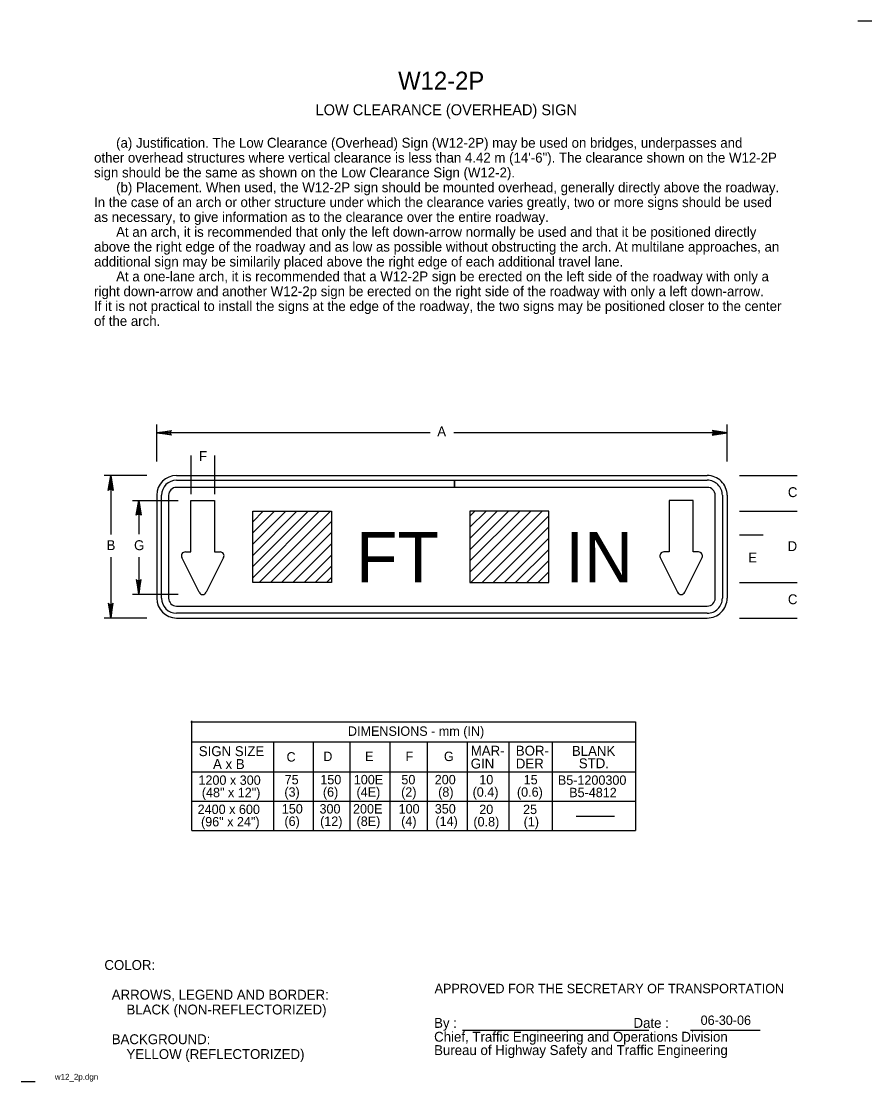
# Model space of a CAD drawing. Extents: x 0.004 to 0.219, y 0.004 to 0.272.
import ezdxf

# ---------------------------------------------------------------- set-up
doc = ezdxf.new("R2010")
doc.units = 0
for name, color, linetype in [('1', 7, 'Continuous'), ('2', 7, 'Continuous'), ('3', 7, 'Continuous'), ('4', 7, 'Continuous'), ('63', 7, 'Continuous')]:
    doc.layers.add(name, color=color, linetype=linetype)

# ---------------------------------------------------------------- blocks, each defined once
blk = doc.blocks.new('RARROW')
at = {"layer": '3'}
for p, q in [((-2.156, 0.28500000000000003), (-2.2665, 0.384625)), ((-2.2665, 0.384625), (0, 0)), ((0, 0), (-2.2665, -0.379125)), ((-2.156, 0.28500000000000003), (-2.075625, 0.12075)), ((0, 0), (-2.156, 0.28500000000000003)), ((-2.14975, -0.2705), (0, 0)), ((-2.075625, 0.12075), (0, 0)), ((0, 0), (-2.074, -0.108)), ((-2.2665, -0.379125), (-2.14975, -0.2705)), ((-2.074, -0.108), (-2.14975, -0.2705))]:
    blk.add_line(p, q, dxfattribs=at)

msp = doc.modelspace()

# ---------------------------------------------------------------- linework, layer by layer
at = {"layer": '1'}
for p, q in [((0.04694523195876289, 0.1620329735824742), (0.04694523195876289, 0.1522708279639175)), ((0.05294523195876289, 0.1620329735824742), (0.05294523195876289, 0.1522708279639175)), ((0.026746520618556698, 0.15700979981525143), (0.026746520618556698, 0.14208944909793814)), ((0.04334899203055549, 0.15580979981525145), (0.1135362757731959, 0.15580979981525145)), ((0.1135362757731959, 0.15580979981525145), (0.1135362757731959, 0.15400979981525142)), ((0.1135362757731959, 0.15400979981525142), (0.1135362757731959, 0.15580979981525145)), ((0.1135362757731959, 0.15580979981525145), (0.17734899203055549, 0.15580979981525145)), ((0.1135362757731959, 0.15400979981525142), (0.04334899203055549, 0.15400979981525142)), ((0.1773489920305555, 0.15400979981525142), (0.1135362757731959, 0.15400979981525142)), ((0.03381359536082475, 0.15070371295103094), (0.03381359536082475, 0.1422092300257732)), ((0.038348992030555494, 0.15200979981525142), (0.038348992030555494, 0.12600979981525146)), ((0.039548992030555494, 0.12600979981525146), (0.039548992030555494, 0.15200979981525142)), ((0.0413489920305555, 0.15200979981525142), (0.0413489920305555, 0.12600979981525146)), ((0.04694523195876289, 0.15071868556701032), (0.05294523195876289, 0.15071868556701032)), ((0.04694523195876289, 0.1377186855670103), (0.04694523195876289, 0.15071868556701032)), ((0.05294523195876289, 0.15071868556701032), (0.0529452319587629, 0.1377186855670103)), ((0.17375275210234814, 0.15071868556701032), (0.16775275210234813, 0.15071868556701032)), ((0.16775275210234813, 0.15071868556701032), (0.16775275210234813, 0.1377186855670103)), ((0.17375275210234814, 0.1377186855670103), (0.17375275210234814, 0.15071868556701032)), ((0.1793489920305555, 0.12600979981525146), (0.17934899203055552, 0.15200979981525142)), ((0.1811489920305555, 0.15200979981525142), (0.18114899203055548, 0.12600979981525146)), ((0.1823489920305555, 0.1520097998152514), (0.1823489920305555, 0.12600979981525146)), ((0.06256101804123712, 0.1453259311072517), (0.06524488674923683, 0.14800979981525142)), ((0.06256101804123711, 0.14249750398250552), (0.06807331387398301, 0.14800979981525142)), ((0.06256101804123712, 0.13966907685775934), (0.07090174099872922, 0.14800979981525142)), ((0.06256101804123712, 0.13684064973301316), (0.07373016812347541, 0.14800979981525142)), ((0.06256101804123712, 0.13401222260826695), (0.07655859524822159, 0.14800979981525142)), ((0.06256101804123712, 0.13118379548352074), (0.07938702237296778, 0.14800979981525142)), ((0.06421544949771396, 0.13000979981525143), (0.08221544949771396, 0.14800979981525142)), ((0.1174206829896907, 0.14675531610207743), (0.1186751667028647, 0.14800979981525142)), ((0.1174206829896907, 0.14392688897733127), (0.12150359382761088, 0.14800979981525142)), ((0.1174206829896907, 0.14109846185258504), (0.12433202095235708, 0.14800979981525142)), ((0.11742068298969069, 0.1382700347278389), (0.12716044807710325, 0.14800979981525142)), ((0.1174206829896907, 0.13544160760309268), (0.12998887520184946, 0.14800979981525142)), ((0.11742068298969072, 0.13261318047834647), (0.13281730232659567, 0.14800979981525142)), ((0.11764572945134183, 0.13000979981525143), (0.13564572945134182, 0.14800979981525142)), ((0.06704387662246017, 0.13000979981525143), (0.08244465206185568, 0.14541057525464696)), ((0.12047415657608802, 0.13000979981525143), (0.13730431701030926, 0.14683996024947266)), ((0.06987230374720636, 0.13000979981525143), (0.08244465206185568, 0.14258214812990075)), ((0.12330258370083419, 0.13000979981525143), (0.13730431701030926, 0.1440115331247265)), ((0.07270073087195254, 0.13000979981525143), (0.08244465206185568, 0.13975372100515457)), ((0.1261310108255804, 0.13000979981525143), (0.13730431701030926, 0.1411831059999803)), ((0.04556326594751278, 0.1377186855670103), (0.04694523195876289, 0.1377186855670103)), ((0.05294523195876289, 0.1377186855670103), (0.05432719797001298, 0.1377186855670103)), ((0.07552915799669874, 0.13000979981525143), (0.08244465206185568, 0.13692529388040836)), ((0.12895943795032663, 0.13000979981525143), (0.13730431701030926, 0.1383546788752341)), ((0.16775275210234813, 0.1377186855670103), (0.16637078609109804, 0.1377186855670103)), ((0.17513471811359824, 0.1377186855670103), (0.17375275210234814, 0.1377186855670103)), ((0.026746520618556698, 0.13633996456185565), (0.026746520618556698, 0.12100979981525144)), ((0.03381359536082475, 0.13633996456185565), (0.03381359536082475, 0.12702699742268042)), ((0.04905080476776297, 0.12750753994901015), (0.04466883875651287, 0.13627147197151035)), ((0.055221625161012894, 0.13627147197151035), (0.0508396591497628, 0.12750753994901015)), ((0.07835758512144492, 0.13000979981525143), (0.08244465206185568, 0.13409686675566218)), ((0.13178786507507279, 0.13000979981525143), (0.13730431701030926, 0.1355262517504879)), ((0.16547635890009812, 0.13627147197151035), (0.1698583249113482, 0.12750753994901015)), ((0.17164717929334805, 0.12750753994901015), (0.17602914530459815, 0.13627147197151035)), ((0.08118601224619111, 0.13000979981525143), (0.0824446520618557, 0.131268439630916)), ((0.134616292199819, 0.13000979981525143), (0.13730431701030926, 0.1326978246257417)), ((0.04334899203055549, 0.12400979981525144), (0.17734899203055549, 0.12400979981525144)), ((0.17734899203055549, 0.12220979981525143), (0.04334899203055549, 0.12220979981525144)), ((0.14420019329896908, 0.07096952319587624), (0.15390244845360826, 0.07096952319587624)), ((0.11556484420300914, 0.01694517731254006), (0.16256818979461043, 0.01694517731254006)), ((0.1730782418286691, 0.01694517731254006), (0.19068984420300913, 0.01694517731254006))]:
    msp.add_line(p, q, dxfattribs=at)
for points in [[(0.08244465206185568, 0.13000979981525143), (0.06256101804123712, 0.13000979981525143), (0.06256101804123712, 0.14800979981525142), (0.08244465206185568, 0.14800979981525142)], [(0.1174206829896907, 0.13000979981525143), (0.13730431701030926, 0.13000979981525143), (0.13730431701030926, 0.14800979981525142), (0.1174206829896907, 0.14800979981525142)]]:
    msp.add_lwpolyline(points, close=True, dxfattribs=at)
for centre, radius, start, end in [((0.04334899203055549, 0.15200979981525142), 0.005, 90, 180), ((0.04334899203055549, 0.15200979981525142), 0.0037999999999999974, 90, 180), ((0.1773489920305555, 0.15200979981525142), 0.005, 1.5631940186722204e-13, 90.00000000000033), ((0.1773489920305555, 0.15200979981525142), 0.0038000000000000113, 0, 90.00000000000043), ((0.04334899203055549, 0.15200979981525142), 0.002, 90, 180), ((0.1773489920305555, 0.15200979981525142), 0.002, 0, 90), ((0.04556326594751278, 0.1367186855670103), 0.001, 90.00000000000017, 206.56505117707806), ((0.05432719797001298, 0.1367186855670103), 0.001, 333.434948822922, 90), ((0.16637078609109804, 0.1367186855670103), 0.001, 90.00000000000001, 206.565051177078), ((0.17513471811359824, 0.1367186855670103), 0.0009999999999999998, 333.4349488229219, 89.99999999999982), ((0.04334899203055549, 0.12600979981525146), 0.005, 180, 270), ((0.04334899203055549, 0.12600979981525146), 0.0037999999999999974, 180, 270), ((0.04334899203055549, 0.12600979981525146), 0.002, 180, 270), ((0.04994523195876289, 0.1279547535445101), 0.001, 206.56505117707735, 333.4349488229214), ((0.17075275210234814, 0.1279547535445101), 0.001, 206.56505117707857, 333.43494882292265), ((0.17734899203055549, 0.12600979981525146), 0.005, 270, 2.2737367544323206e-13), ((0.17734899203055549, 0.12600979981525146), 0.002, 270, 3.979039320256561e-13), ((0.17734899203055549, 0.12600979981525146), 0.0038000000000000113, 270, 2.2737367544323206e-13)]:
    msp.add_arc(centre, radius, start, end, dxfattribs=at)
at = {"layer": '3'}
for p, q in [((0.03834899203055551, 0.160544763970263), (0.03834899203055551, 0.1699298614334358)), ((0.18234899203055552, 0.160544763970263), (0.18234899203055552, 0.1699298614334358)), ((0.10735908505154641, 0.16779008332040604), (0.03834899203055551, 0.16779008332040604)), ((0.1823489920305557, 0.16779008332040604), (0.113348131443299, 0.16779008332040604)), ((0.03584987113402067, 0.15700979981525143), (0.025069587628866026, 0.15700979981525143)), ((0.04334899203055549, 0.15700979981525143), (0.17734899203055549, 0.15700979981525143)), ((0.1854562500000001, 0.15700979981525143), (0.20006952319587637, 0.15700979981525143)), ((0.032256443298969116, 0.15070371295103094), (0.04375541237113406, 0.15070371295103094)), ((0.1854562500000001, 0.14800979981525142), (0.20006952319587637, 0.14800979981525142)), ((0.19144529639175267, 0.14193972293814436), (0.1854562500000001, 0.14193972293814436)), ((0.1854562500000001, 0.13000979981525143), (0.20006952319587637, 0.13000979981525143)), ((0.032256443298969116, 0.12702699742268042), (0.04375541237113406, 0.12702699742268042)), ((0.03584987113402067, 0.12100979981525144), (0.025069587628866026, 0.12100979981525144)), ((0.04334899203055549, 0.12100979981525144), (0.17734899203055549, 0.12100979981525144)), ((0.1854562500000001, 0.12100979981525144), (0.20006952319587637, 0.12100979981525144)), ((0.04692099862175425, 0.0947543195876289), (0.15923269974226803, 0.0947543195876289)), ((0.04715691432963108, 0.0950130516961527), (0.04715691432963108, 0.06737931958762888)), ((0.15923269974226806, 0.09482276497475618), (0.15923269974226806, 0.06737931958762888)), ((0.15923269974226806, 0.08962826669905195), (0.04715691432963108, 0.08962826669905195)), ((0.06777970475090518, 0.08962826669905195), (0.06777970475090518, 0.06737931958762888)), ((0.08709587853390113, 0.08962826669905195), (0.08709587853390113, 0.06737931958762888)), ((0.12727758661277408, 0.08962826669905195), (0.12727758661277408, 0.06737931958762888)), ((0.13821075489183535, 0.08962826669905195), (0.13821075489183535, 0.06737931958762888)), ((0.04715691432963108, 0.08212931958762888), (0.15923269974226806, 0.08212931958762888)), ((0.04717099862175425, 0.07475431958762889), (0.15923269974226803, 0.07475431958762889)), ((0.04718508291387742, 0.06737931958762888), (0.15923269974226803, 0.06737931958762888))]:
    msp.add_line(p, q, dxfattribs=at)
for points in [[(0.07780691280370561, 0.08962826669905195), (0.07780691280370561, 0.06737931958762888)], [(0.09719954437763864, 0.08962826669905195), (0.09719954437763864, 0.06737931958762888)], [(0.10664263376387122, 0.08962826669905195), (0.10664263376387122, 0.06737931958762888)], [(0.11668052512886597, 0.08962826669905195), (0.11668052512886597, 0.06737931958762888)]]:
    msp.add_lwpolyline(points, dxfattribs=at)
at = {"layer": '63'}
for p, q in [((0.21887500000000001, 0.27175), (0.215375, 0.27175)), ((0.21887500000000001, 0.27175), (0.215375, 0.27175)), ((0.007625, 0.003875), (0.004125, 0.003875)), ((0.007625, 0.003875), (0.004125, 0.003875))]:
    msp.add_line(p, q, dxfattribs=at)

# ---------------------------------------------------------------- block references
at = {"layer": '3', "xscale": 0.0016545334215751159}
for p, yscale, rotation in [((0.03834899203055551, 0.16779008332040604), 0.0016366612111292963, 180), ((0.026746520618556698, 0.15700979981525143), 0.0016366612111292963, 89.99999999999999), ((0.03381359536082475, 0.15070371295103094), 0.0016366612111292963, 89.99999999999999), ((0.03381359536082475, 0.12702699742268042), -0.0016366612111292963, -89.99999999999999), ((0.026746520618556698, 0.12100979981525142), -0.0016366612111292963, -89.99999999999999)]:
    msp.add_blockref('RARROW', p, dxfattribs=dict(at, yscale=yscale, rotation=rotation))
at = {"layer": '3', "xscale": 0.0016545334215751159, "yscale": -0.0016366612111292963}
msp.add_blockref('RARROW', (0.18234899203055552, 0.16779008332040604), dxfattribs=at)

# ---------------------------------------------------------------- texts
at = {"layer": '1'}
for s, height, p in [('W12-2P', 0.0045000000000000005, (0.09929318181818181, 0.2545)), ('LOW CLEARANCE (OVERHEAD) SIGN', 0.00275025, (0.0784403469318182, 0.248)), ('COLOR:', 0.0024997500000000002, (0.025125, 0.032125)), ('  ARROWS, LEGEND AND BORDER:', 0.0024997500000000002, (0.025125, 0.0246255)), ('APPROVED FOR THE SECRETARY OF TRANSPORTATION', 0.0023752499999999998, (0.1085, 0.02625)), ('      BLACK (NON-REFLECTORIZED)', 0.0024997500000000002, (0.025125, 0.020875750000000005)), ('By :                                                Date :', 0.0024997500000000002, (0.108375, 0.0175)), ('Chief, Traffic Engineering and Operations Division', 0.0024997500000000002, (0.108375, 0.014)), ('  BACKGROUND:', 0.0024997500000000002, (0.025125, 0.01337625)), ('      YELLOW (REFLECTORIZED)', 0.0024997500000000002, (0.025125, 0.0096265)), ('Bureau of Highway Safety and Traffic Engineering', 0.0024997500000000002, (0.108375, 0.010625)), ('w12_2p.dgn', 0.0015, (0.012625, 0.004375))]:
    msp.add_text(s, height=height, dxfattribs=at).set_placement(p)
at = {"layer": '2'}
for s, p in [('      (a) Justification. The Low Clearance (Overhead) Sign (W12-2P) may be used on bridges, underpasses and', (0.02251589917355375, 0.23979256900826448)), ('other overhead structures where vertical clearance is less than 4.42 m (14\'-6"). The clearance shown on the W12-2P', (0.02251589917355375, 0.2360428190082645)), ('sign should be the same as shown on the Low Clearance Sign (W12-2).', (0.02251589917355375, 0.23229306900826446)), ('      (b) Placement. When used, the W12-2P sign should be mounted overhead, generally directly above the roadway.', (0.02251589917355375, 0.2285433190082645)), ('In the case of an arch or other structure under which the clearance varies greatly, two or more signs should be used', (0.02251589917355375, 0.2247935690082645)), ('as necessary, to give information as to the clearance over the entire roadway.', (0.02251589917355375, 0.22104381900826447)), ('      At an arch, it is recommended that only the left down-arrow normally be used and that it be positioned directly', (0.02251589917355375, 0.21729406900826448)), ('above the right edge of the roadway and as low as possible without obstructing the arch. At multilane approaches, an', (0.02251589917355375, 0.21354431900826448)), ('additional sign may be similarily placed above the right edge of each additional travel lane.', (0.02251589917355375, 0.2097945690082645)), ('      At a one-lane arch, it is recommended that a W12-2P sign be erected on the left side of the roadway with only a ', (0.02251589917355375, 0.2060448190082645)), ('right down-arrow and another W12-2p sign be erected on the right side of the roadway with only a left down-arrow.', (0.02251589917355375, 0.2022950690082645)), ('If it is not practical to install the signs at the edge of the roadway, the two signs may be positioned closer to the center', (0.02251589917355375, 0.19854531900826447)), ('of the arch.', (0.02251589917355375, 0.19479556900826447))]:
    msp.add_text(s, height=0.0024997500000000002, dxfattribs=at).set_placement(p)
at = {"layer": '3'}
for s, height, p in [('A', 0.0024997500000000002, (0.10916521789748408, 0.16690221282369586)), ('F', 0.0024997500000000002, (0.049018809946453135, 0.16067360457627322)), ('FT', 0.012748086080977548, (0.08871760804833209, 0.130011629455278)), ('IN', 0.012748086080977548, (0.1414936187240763, 0.130011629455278)), ('B', 0.0024997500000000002, (0.025662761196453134, 0.13815479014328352)), ('G', 0.0024997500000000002, (0.03261346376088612, 0.13815479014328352)), ('D', 0.0024997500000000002, (0.1976208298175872, 0.13791522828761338)), ('SIGN SIZE', 0.0024997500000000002, (0.04895740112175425, 0.08612931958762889)), ('MAR-', 0.0024997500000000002, (0.11762544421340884, 0.08625431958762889)), ('BOR-', 0.0024997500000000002, (0.12900044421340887, 0.08625431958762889)), ('BLANK', 0.0024997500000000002, (0.1431540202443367, 0.08619442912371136)), ('C', 0.0023752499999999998, (0.07111675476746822, 0.08474910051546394)), ('D', 0.0023752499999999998, (0.08039622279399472, 0.08487931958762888)), ('F', 0.0023752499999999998, (0.10115573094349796, 0.08487931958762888)), ('G', 0.0023752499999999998, (0.11085902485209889, 0.08487931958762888)), ('A x B', 0.0024997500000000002, (0.05255401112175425, 0.08287956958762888)), ('GIN', 0.0024997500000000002, (0.11762544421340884, 0.08300431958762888)), ('DER', 0.0024997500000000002, (0.12900044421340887, 0.08300431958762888)), ('STD.', 0.0024997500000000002, (0.1449040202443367, 0.08306942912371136)), ('1200 x 300', 0.0023752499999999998, (0.04887369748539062, 0.0788793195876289)), ('75', 0.0023752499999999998, (0.07063524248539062, 0.0790043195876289)), ('150', 0.0023752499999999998, (0.07963945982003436, 0.0790043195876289)), ('50', 0.0023752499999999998, (0.10010676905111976, 0.0790043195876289)), ('10', 0.0023752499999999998, (0.11977682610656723, 0.07899910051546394)), ('B5-1200300', 0.0023752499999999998, (0.13961226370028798, 0.0788793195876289)), ('(48" x 12")', 0.0023752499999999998, (0.04972410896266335, 0.0757540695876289)), ('(3)', 0.0023752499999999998, (0.07056002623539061, 0.0758790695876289)), ('(6)', 0.0023752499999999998, (0.08029193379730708, 0.0758790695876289)), ('(2)', 0.0023752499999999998, (0.10003947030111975, 0.0758790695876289)), ('(0.4)', 0.0023752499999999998, (0.1180900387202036, 0.07587385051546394)), ('B5-4812', 0.0023752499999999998, (0.1424758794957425, 0.0757540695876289)), ('2400 x 600', 0.0023752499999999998, (0.04867184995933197, 0.07150431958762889)), ('150', 0.0023752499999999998, (0.06992163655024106, 0.07162931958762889)), ('300', 0.0023752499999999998, (0.07943761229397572, 0.07162931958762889)), ('100', 0.0023752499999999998, (0.09940108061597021, 0.07162931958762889)), ('25', 0.0023752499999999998, (0.1308328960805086, 0.07149910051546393)), ('(96" x 24")', 0.0023752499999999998, (0.049522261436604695, 0.06837906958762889)), ('(6)', 0.0023752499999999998, (0.07057411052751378, 0.06850406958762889)), ('(12)', 0.0023752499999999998, (0.07958624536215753, 0.06850406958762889)), ('(4)', 0.0023752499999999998, (0.10005355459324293, 0.06850406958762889)), ('(1)', 0.0023752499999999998, (0.1309736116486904, 0.06837385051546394))]:
    msp.add_text(s, height=height, dxfattribs=at).set_placement(p)
for s, height, p in [('C', 0.0024997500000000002, (0.19769241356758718, 0.1515496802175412)), ('E', 0.0024997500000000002, (0.18767865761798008, 0.13504048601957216)), ('C', 0.0024997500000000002, (0.19769241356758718, 0.12449976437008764)), ('DIMENSIONS - mm (IN)', 0.0023752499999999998, (0.08661681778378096, 0.09125431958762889)), ('E', 0.0023752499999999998, (0.09093412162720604, 0.08487931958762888)), ('100E', 0.0023752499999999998, (0.08809619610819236, 0.0790043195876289)), ('200', 0.0023752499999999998, (0.10852980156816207, 0.0790043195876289)), ('15', 0.0023752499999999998, (0.13097908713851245, 0.07899334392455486)), ('(4E)', 0.0023752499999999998, (0.08877998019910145, 0.0758790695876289)), ('(8)', 0.0023752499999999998, (0.1093982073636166, 0.0758790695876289)), ('(0.6)', 0.0023752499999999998, (0.12928438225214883, 0.07587960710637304)), ('200E', 0.0023752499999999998, (0.08789434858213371, 0.07162931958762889)), ('350', 0.0023752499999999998, (0.10854388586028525, 0.07162931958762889)), ('20', 0.0023752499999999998, (0.11975983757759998, 0.07149910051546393)), ('(8E)', 0.0023752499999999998, (0.08879406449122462, 0.06850406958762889)), ('(14)', 0.0023752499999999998, (0.10869251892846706, 0.06850406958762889)), ('(0.8)', 0.0023752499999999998, (0.11828898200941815, 0.06837385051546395))]:
    msp.add_text(s, height=height, rotation=360, dxfattribs=at).set_placement(p)
at = {"layer": '4'}
msp.add_text('06-30-06', height=0.0023752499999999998, dxfattribs=at).set_placement((0.17566378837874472, 0.018237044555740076))

doc.saveas('drawing.dxf')
